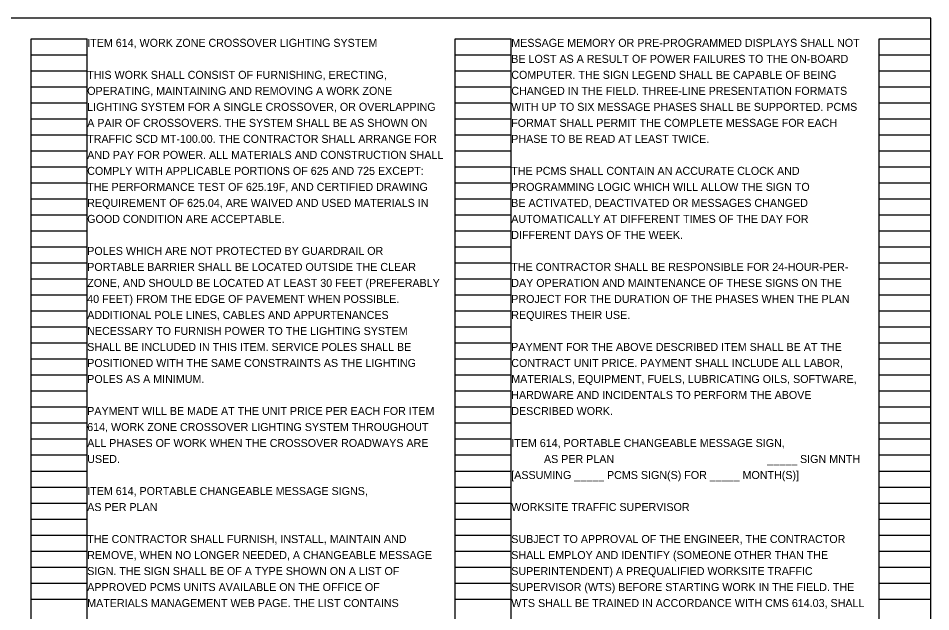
# Model space of a CAD drawing. Extents: x -34 to 2132911, y 0 to 658646.
# Drawn here: x 50.03 to 66, y 11.12 to 21.5 of the extents above; entities that cross this region are included whole.
import ezdxf

# ---------------------------------------------------------------- set-up
doc = ezdxf.new("R2010")
doc.units = 0
for name, color, linetype in [('SC_Scratch1', 7, 'Continuous'), ('SH_Data', 7, 'Continuous'), ('SH_Text', 7, 'Continuous')]:
    doc.layers.add(name, color=color, linetype=linetype)

msp = doc.modelspace()

# ---------------------------------------------------------------- linework, layer by layer
at = {"layer": 'SC_Scratch1'}
msp.add_lwpolyline([(35.5, 0.5), (66, 0.5), (66, 21.5), (35.5, 21.5)], close=True, dxfattribs=at)
at = {"layer": 'SH_Data'}
for p, q in [((50.26, 0.98), (50.26, 21.14)), ((50.26, 21.14), (51.24, 21.14)), ((51.24, 0.98), (51.24, 21.14)), ((57.68, 0.98), (57.68, 21.14)), ((57.68, 21.14), (58.66, 21.14)), ((58.66, 0.98), (58.66, 21.14)), ((65.1, 0.98), (65.1, 21.14)), ((65.1, 21.14), (66, 21.14)), ((66, 0.98), (66, 21.14)), ((50.26, 20.86), (51.24, 20.86)), ((57.68, 20.86), (58.66, 20.86)), ((65.1, 20.86), (66, 20.86)), ((50.26, 20.58), (51.24, 20.58)), ((57.68, 20.58), (58.66, 20.58)), ((65.1, 20.58), (66, 20.58)), ((50.26, 20.3), (51.24, 20.3)), ((57.68, 20.3), (58.66, 20.3)), ((65.1, 20.3), (66, 20.3)), ((50.26, 20.02), (51.24, 20.02)), ((57.68, 20.02), (58.66, 20.02)), ((65.1, 20.02), (66, 20.02)), ((50.26, 19.74), (51.24, 19.74)), ((57.68, 19.74), (58.66, 19.74)), ((65.1, 19.74), (66, 19.74)), ((50.26, 19.46), (51.24, 19.46)), ((57.68, 19.46), (58.66, 19.46)), ((65.1, 19.46), (66, 19.46)), ((50.26, 19.18), (51.24, 19.18)), ((57.68, 19.18), (58.66, 19.18)), ((65.1, 19.18), (66, 19.18)), ((50.26, 18.9), (51.24, 18.9)), ((57.68, 18.9), (58.66, 18.9)), ((65.1, 18.9), (66, 18.9)), ((50.26, 18.62), (51.24, 18.62)), ((57.68, 18.62), (58.66, 18.62)), ((65.1, 18.62), (66, 18.62)), ((50.26, 18.34), (51.24, 18.34)), ((57.68, 18.34), (58.66, 18.34)), ((65.1, 18.34), (66, 18.34)), ((50.26, 18.06), (51.24, 18.06)), ((57.68, 18.06), (58.66, 18.06)), ((65.1, 18.06), (66, 18.06)), ((50.26, 17.78), (51.24, 17.78)), ((57.68, 17.78), (58.66, 17.78)), ((65.1, 17.78), (66, 17.78)), ((50.26, 17.5), (51.24, 17.5)), ((57.68, 17.5), (58.66, 17.5)), ((65.1, 17.5), (66, 17.5)), ((50.26, 17.22), (51.24, 17.22)), ((57.68, 17.22), (58.66, 17.22)), ((65.1, 17.22), (66, 17.22)), ((50.26, 16.94), (51.24, 16.94)), ((57.68, 16.94), (58.66, 16.94)), ((65.1, 16.94), (66, 16.94)), ((50.26, 16.66), (51.24, 16.66)), ((57.68, 16.66), (58.66, 16.66)), ((65.1, 16.66), (66, 16.66)), ((50.26, 16.38), (51.24, 16.38)), ((57.68, 16.38), (58.66, 16.38)), ((65.1, 16.38), (66, 16.38)), ((50.26, 16.1), (51.24, 16.1)), ((57.68, 16.1), (58.66, 16.1)), ((65.1, 16.1), (66, 16.1)), ((50.26, 15.82), (51.24, 15.82)), ((57.68, 15.82), (58.66, 15.82)), ((65.1, 15.82), (66, 15.82)), ((50.26, 15.54), (51.24, 15.54)), ((57.68, 15.54), (58.66, 15.54)), ((65.1, 15.54), (66, 15.54)), ((50.26, 15.26), (51.24, 15.26)), ((57.68, 15.26), (58.66, 15.26)), ((65.1, 15.26), (66, 15.26)), ((50.26, 14.98), (51.24, 14.98)), ((57.68, 14.98), (58.66, 14.98)), ((65.1, 14.98), (66, 14.98)), ((50.26, 14.7), (51.24, 14.7)), ((57.68, 14.7), (58.66, 14.7)), ((65.1, 14.7), (66, 14.7)), ((50.26, 14.42), (51.24, 14.42)), ((57.68, 14.42), (58.66, 14.42)), ((65.1, 14.42), (66, 14.42)), ((50.26, 14.14), (51.24, 14.14)), ((57.68, 14.14), (58.66, 14.14)), ((65.1, 14.14), (66, 14.14)), ((50.26, 13.86), (51.24, 13.86)), ((57.68, 13.86), (58.66, 13.86)), ((65.1, 13.86), (66, 13.86)), ((50.26, 13.58), (51.24, 13.58)), ((57.68, 13.58), (58.66, 13.58)), ((65.1, 13.58), (66, 13.58)), ((50.26, 13.3), (51.24, 13.3)), ((57.68, 13.3), (58.66, 13.3)), ((65.1, 13.3), (66, 13.3)), ((50.26, 13.02), (51.24, 13.02)), ((57.68, 13.02), (58.66, 13.02)), ((65.1, 13.02), (66, 13.02)), ((50.26, 12.74), (51.24, 12.74)), ((57.68, 12.74), (58.66, 12.74)), ((65.1, 12.74), (66, 12.74)), ((50.26, 12.46), (51.24, 12.46)), ((57.68, 12.46), (58.66, 12.46)), ((65.1, 12.46), (66, 12.46)), ((50.26, 12.18), (51.24, 12.18)), ((57.68, 12.18), (58.66, 12.18)), ((65.1, 12.18), (66, 12.18)), ((50.26, 11.9), (51.24, 11.9)), ((57.68, 11.9), (58.66, 11.9)), ((65.1, 11.9), (66, 11.9)), ((50.26, 11.62), (51.24, 11.62)), ((57.68, 11.62), (58.66, 11.62)), ((65.1, 11.62), (66, 11.62)), ((50.26, 11.34), (51.24, 11.34)), ((57.68, 11.34), (58.66, 11.34)), ((65.1, 11.34), (66, 11.34))]:
    msp.add_line(p, q, dxfattribs=at)

# ---------------------------------------------------------------- texts
at = {"layer": 'SH_Text'}
for s, p in [('ITEM 614, WORK ZONE CROSSOVER LIGHTING SYSTEM', (51.24, 21)), ('MESSAGE MEMORY OR PRE-PROGRAMMED DISPLAYS SHALL NOT', (58.66, 21)), ('BE LOST AS A RESULT OF POWER FAILURES TO THE ON-BOARD', (58.66, 20.72)), ('THIS WORK SHALL CONSIST OF FURNISHING, ERECTING,', (51.24, 20.44)), ('COMPUTER. THE SIGN LEGEND SHALL BE CAPABLE OF BEING', (58.66, 20.44)), ('OPERATING, MAINTAINING AND REMOVING A WORK ZONE', (51.24, 20.16)), ('CHANGED IN THE FIELD. THREE-LINE PRESENTATION FORMATS', (58.66, 20.16)), ('LIGHTING SYSTEM FOR A SINGLE CROSSOVER, OR OVERLAPPING', (51.24, 19.88)), ('WITH UP TO SIX MESSAGE PHASES SHALL BE SUPPORTED. PCMS', (58.66, 19.88)), ('A PAIR OF CROSSOVERS. THE SYSTEM SHALL BE AS SHOWN ON', (51.24, 19.6)), ('FORMAT SHALL PERMIT THE COMPLETE MESSAGE FOR EACH', (58.66, 19.6)), ('TRAFFIC SCD MT-100.00. THE CONTRACTOR SHALL ARRANGE FOR', (51.24, 19.32)), ('PHASE TO BE READ AT LEAST TWICE.', (58.66, 19.32)), ('AND PAY FOR POWER. ALL MATERIALS AND CONSTRUCTION SHALL', (51.24, 19.04)), ('COMPLY WITH APPLICABLE PORTIONS OF 625 AND 725 EXCEPT:', (51.24, 18.76)), ('THE PCMS SHALL CONTAIN AN ACCURATE CLOCK AND', (58.66, 18.76)), ('THE PERFORMANCE TEST OF 625.19F, AND CERTIFIED DRAWING', (51.24, 18.48)), ('PROGRAMMING LOGIC WHICH WILL ALLOW THE SIGN TO', (58.66, 18.48)), ('REQUIREMENT OF 625.04, ARE WAIVED AND USED MATERIALS IN', (51.24, 18.2)), ('BE ACTIVATED, DEACTIVATED OR MESSAGES CHANGED', (58.66, 18.2)), ('GOOD CONDITION ARE ACCEPTABLE.', (51.24, 17.92)), ('AUTOMATICALLY AT DIFFERENT TIMES OF THE DAY FOR', (58.66, 17.92)), ('DIFFERENT DAYS OF THE WEEK.', (58.66, 17.64)), ('POLES WHICH ARE NOT PROTECTED BY GUARDRAIL OR', (51.24, 17.36)), ('PORTABLE BARRIER SHALL BE LOCATED OUTSIDE THE CLEAR', (51.24, 17.08)), ('THE CONTRACTOR SHALL BE RESPONSIBLE FOR 24-HOUR-PER-', (58.66, 17.08)), ('ZONE, AND SHOULD BE LOCATED AT LEAST 30 FEET (PREFERABLY', (51.24, 16.8)), ('DAY OPERATION AND MAINTENANCE OF THESE SIGNS ON THE', (58.66, 16.8)), ('40 FEET) FROM THE EDGE OF PAVEMENT WHEN POSSIBLE.', (51.24, 16.52)), ('PROJECT FOR THE DURATION OF THE PHASES WHEN THE PLAN', (58.66, 16.52)), ('ADDITIONAL POLE LINES, CABLES AND APPURTENANCES', (51.24, 16.24)), ('REQUIRES THEIR USE.', (58.66, 16.24)), ('NECESSARY TO FURNISH POWER TO THE LIGHTING SYSTEM', (51.24, 15.96)), ('SHALL BE INCLUDED IN THIS ITEM. SERVICE POLES SHALL BE', (51.24, 15.68)), ('PAYMENT FOR THE ABOVE DESCRIBED ITEM SHALL BE AT THE', (58.66, 15.68)), ('POSITIONED WITH THE SAME CONSTRAINTS AS THE LIGHTING', (51.24, 15.4)), ('CONTRACT UNIT PRICE. PAYMENT SHALL INCLUDE ALL LABOR,', (58.66, 15.4)), ('POLES AS A MINIMUM.', (51.24, 15.12)), ('MATERIALS, EQUIPMENT, FUELS, LUBRICATING OILS, SOFTWARE,', (58.66, 15.12)), ('HARDWARE AND INCIDENTALS TO PERFORM THE ABOVE', (58.66, 14.84)), ('PAYMENT WILL BE MADE AT THE UNIT PRICE PER EACH FOR ITEM', (51.24, 14.56)), ('DESCRIBED WORK.', (58.66, 14.56)), ('614, WORK ZONE CROSSOVER LIGHTING SYSTEM THROUGHOUT', (51.24, 14.28)), ('ALL PHASES OF WORK WHEN THE CROSSOVER ROADWAYS ARE', (51.24, 14)), ('ITEM 614, PORTABLE CHANGEABLE MESSAGE SIGN,', (58.66, 14)), ('USED.', (51.24, 13.72)), ('           AS PER PLAN ', (58.66, 13.72)), ('_____ SIGN MNTH', (63.14, 13.72)), ('[ASSUMING _____ PCMS SIGN(S) FOR _____ MONTH(S)]', (58.66, 13.44)), ('ITEM 614, PORTABLE CHANGEABLE MESSAGE SIGNS,', (51.24, 13.16)), ('AS PER PLAN', (51.24, 12.88)), ('WORKSITE TRAFFIC SUPERVISOR', (58.66, 12.88)), ('THE CONTRACTOR SHALL FURNISH, INSTALL, MAINTAIN AND', (51.24, 12.32)), ('SUBJECT TO APPROVAL OF THE ENGINEER, THE CONTRACTOR', (58.66, 12.32)), ('REMOVE, WHEN NO LONGER NEEDED, A CHANGEABLE MESSAGE', (51.24, 12.04)), ('SHALL EMPLOY AND IDENTIFY (SOMEONE OTHER THAN THE', (58.66, 12.04)), ('SIGN. THE SIGN SHALL BE OF A TYPE SHOWN ON A LIST OF', (51.24, 11.76)), ('SUPERINTENDENT) A PREQUALIFIED WORKSITE TRAFFIC', (58.66, 11.76)), ('APPROVED PCMS UNITS AVAILABLE ON THE OFFICE OF', (51.24, 11.48)), ('SUPERVISOR (WTS) BEFORE STARTING WORK IN THE FIELD. THE', (58.66, 11.48)), ('MATERIALS MANAGEMENT WEB PAGE. THE LIST CONTAINS', (51.24, 11.2)), ('WTS SHALL BE TRAINED IN ACCORDANCE WITH CMS 614.03, SHALL', (58.66, 11.2))]:
    msp.add_text(s, height=0.14, dxfattribs=at).set_placement(p)

doc.saveas('drawing.dxf')
